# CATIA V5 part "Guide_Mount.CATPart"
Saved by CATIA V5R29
Part number: Guide_Mount
Source: Unknown
Bounding box of the stored display mesh (mm): x -50 to 50, y 0 to 30, z -45 to 45
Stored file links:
  C:\Users\Administrator\Desktop\프로젝트\Boxfold\Guide\Guide_Mount.CATPart
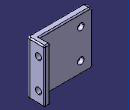
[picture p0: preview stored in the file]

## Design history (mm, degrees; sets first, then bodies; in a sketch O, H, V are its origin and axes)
Body1 (main body)
  Solid1 "PartBody": solid without history
  RemoveFace1: RemoveFaces (face of Solid1; face of Solid1), deactivated
  RemoveFace2: RemoveFaces face of Solid1, deactivated
  Sketch1 on face of Solid1, origin (0, 12, 0), H (-1, 0, 0), V (0, 0, 1)
    circle A1 centre (30, 25) radius 5.25
    reference projected arc E1 centre (30, 25) radius 5.25 from (35.25, 25) to (24.75, 25) ccw from edge [face of Solid1 | face of Solid1]
    circle A2 centre (30, -25) radius 5.25
    reference projected arc E2 centre (30, -25) radius 5.25 from (35.25, -25) to (24.75, -25) ccw from edge [face of Solid1 | face of Solid1]
    coincidence: A1 E1, A2 E2
  Pad1: profile Sketch1, direction (0, -1, 0), up to face of Solid1
  DatumCurve1
  DatumCurve2
  DatumSurface1
  Sketch2 on face of Solid1, origin (40, 0, 0), H (0, 0, 1), V (0, 1, 0)
    circle A1 centre (25, 20) radius 5.25
    point P1 (25, 20)
    reference projected point E1 (25, 72) from edge of DatumCurve1
    reference projected point E2 (25, 72) from edge of DatumCurve2
    circle A2 centre (-25, 20) radius 5.25
    radius A1 = 5.25
    distance E1 P1 V = 52
    distance P1 E2 H = 0
    symmetry: A1 A2 V
  Pocket1: profile Sketch2, direction (1, 0, 0), through (limit type 6)
  DatumSurface2
  Sketch3 on face of Solid1, origin (40, 0, 0), H (0, 0, 1), V (0, 1, 0)
    line L1 (-45, 30) -> (45, 30)
    line L2 (45, 30) -> (45, 92)
    line L3 (45, 92) -> (-45, 92)
    line L4 (-45, 92) -> (-45, 30)
    reference projected point E1 (25, 20) from axis of face of Pocket1 from Sketch2.A1
    reference intersected line E2 (45, 10) -> (45, 2) from face of Solid1
    reference intersected line E3 (-45, 2) -> (-45, 10) from face of Solid1
    reference intersected line E4 through (0, 92) direction (-1, 0) from face of Solid1
    distance L1 E1 = 10
    horizontal: L1 H, L3 H
    vertical: L2 V, L4 V
    coincidence: L2 E2, L4 E3, L3 E4
  Pocket2: profile Sketch3, direction (1, 0, 0), through (limit type 6)
  Fillet1: radius 2, on face of Pocket2 from Sketch3.L1
  DatumCurve3
  DatumCurve4
  Sketch4 on face of Solid1, origin (-30.2681, 12, -31.0392), H (1, 0, 0), V (0, 0, -1)
    point P1 (0.2681, -6.0392)
    reference projected line E1 (130.2681, -6.0392) -> (54.2681, -6.0392) from edge of DatumCurve3
    reference projected line E2 (0.2681, -376.0392) -> (0.2681, 623.9608) from edge of DatumCurve4
    coincidence: E1 P1, P1 E2
  Hole1: placed by Sketch4, at (-30, 12, -25) direction (0, -1, 0), diameter 6.6, through (limit type 6), counterbore diameter 11, counterbore depth 6.5
  DatumCurve5
  DatumCurve6
  Sketch5 on face of Solid1, origin (-9.6299, 12, 15.1043), H (1, 0, 0), V (0, 0, -1)
    point P1 (-20.3701, -9.8957)
    reference projected line E1 through (0, -9.8957) direction (1, 0) from edge of DatumCurve5
    reference projected line E2 (-20.3701, -329.8957) -> (-20.3701, 670.1043) from edge of DatumCurve6
    coincidence: E1 P1, P1 E2
  Hole2: placed by Sketch5, at (-30, 12, 25) direction (0, -1, 0), diameter 6.6, through (limit type 6), counterbore diameter 11, counterbore depth 6.5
